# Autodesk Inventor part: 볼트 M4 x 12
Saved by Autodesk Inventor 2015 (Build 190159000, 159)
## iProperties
Created: 2025-08
Part Number: 볼트 M4 x 12
Material: 일반
Document SubType Name: Modeling
Designer: user
Density: 1 g/cm^3
Appearance: 기본값
Author: user
Author: jhkim
Description: 6각머리 태핑 나사
Creation Date: 2025-08-05
Sending System: Autodesk Inventor 2026
Preprocessor: ST-DEVELOPER v20.1
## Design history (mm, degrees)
node "볼트 M4 x 121"
body "Solid1"
node "기준1"
